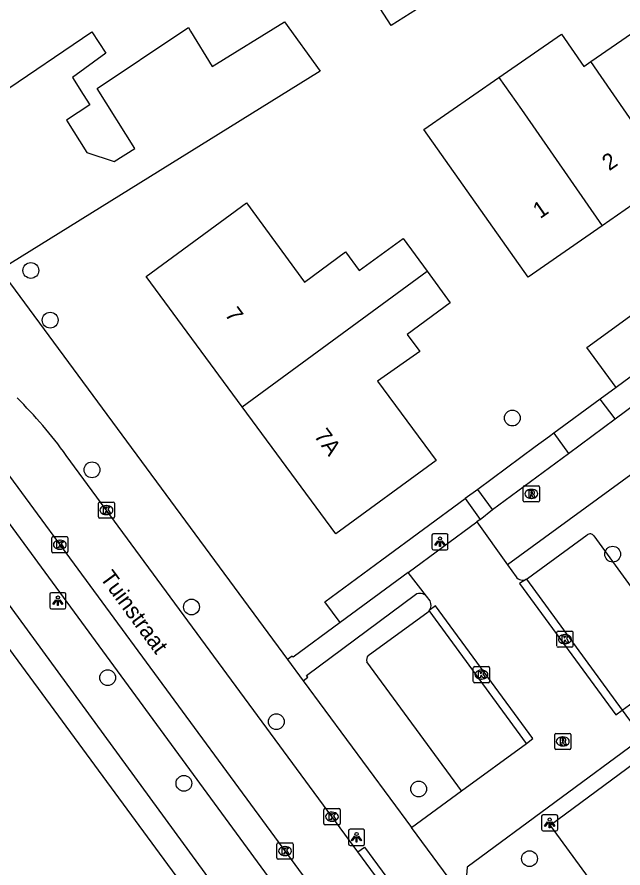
# Model space of a CAD drawing. Extents: x 161801 to 162379, y 382315 to 382832.
# Drawn here: x 161967 to 162004.5, y 382446.1 to 382498.8 of the extents above; entities that cross this region are included whole.
import ezdxf

# ---------------------------------------------------------------- set-up
doc = ezdxf.new("R2010")
doc.units = 0
for name, color, linetype in [('IMGEO_Boom', 7, 'Continuous'), ('IMGEO_Groenvoorziening', 7, 'Continuous'), ('IMGEO_Kolk', 7, 'Continuous'), ('IMGEO_Lichtpunt', 7, 'Continuous'), ('IMGEO_Openbare_ruimte_label', 7, 'Continuous'), ('IMGEO_Pand', 7, 'Continuous'), ('IMGEO_Pand_nummerreeks', 7, 'Continuous'), ('IMGEO_Parkeervlak_open', 7, 'Continuous'), ('IMGEO_Rijbaan_lokaal_open', 7, 'Continuous'), ('IMGEO_Rioolput', 7, 'Continuous'), ('IMGEO_Voetpad_open', 7, 'Continuous')]:
    doc.layers.add(name, color=color, linetype=linetype)

msp = doc.modelspace()

# ---------------------------------------------------------------- linework, layer by layer
at = {"layer": 'IMGEO_Boom'}
for centre in [(161967.865, 382483.121), (161969.063, 382480.043), (161997.697, 382473.976), (161971.654, 382470.771), (162003.909, 382465.545), (161977.814, 382462.27), (161972.621, 382457.894), (161983.07, 382455.167), (161977.348, 382451.352), (161991.892, 382450.996), (161998.756, 382446.683)]:
    msp.add_circle(centre, 0.489, dxfattribs=at)
at = {"layer": 'IMGEO_Groenvoorziening'}
for points in [[(162004.124, 382475.871), (162003.145, 382475.15)], [(162000.27, 382473.035), (162000, 382472.836), (161999.114, 382472.184), (161995.546, 382469.558)], [(161987.033, 382461.316), (161986.084, 382462.594), (161989.614, 382465.192), (161994.772, 382468.988)]]:
    msp.add_lwpolyline(points, dxfattribs=at)
at = {"layer": 'IMGEO_Kolk'}
for p, q in [((161972.046, 382467.848), (161972.046, 382468.7)), ((161972.121, 382468.774), (161972.973, 382468.774)), ((161972.534, 382468.554), (161972.559, 382468.554)), ((161973.047, 382468.7), (161973.047, 382467.848)), ((161972.557, 382467.994), (161972.532, 382467.994)), ((161972.973, 382467.774), (161972.121, 382467.774)), ((161969.16, 382465.704), (161969.16, 382466.556)), ((161969.235, 382466.63), (161970.087, 382466.63)), ((161969.648, 382466.41), (161969.673, 382466.41)), ((161970.161, 382466.556), (161970.161, 382465.704)), ((161970.087, 382465.63), (161969.235, 382465.63)), ((161969.671, 382465.85), (161969.646, 382465.85)), ((162000.451, 382459.856), (162000.451, 382460.708)), ((162000.526, 382460.782), (162001.378, 382460.782)), ((162001.452, 382460.708), (162001.452, 382459.856)), ((162000.939, 382460.562), (162000.964, 382460.562)), ((162001.378, 382459.782), (162000.526, 382459.782)), ((162000.962, 382460.002), (162000.937, 382460.002)), ((161995.277, 382457.657), (161995.277, 382458.509)), ((161995.352, 382458.583), (161996.204, 382458.583)), ((161996.278, 382458.509), (161996.278, 382457.657)), ((161995.765, 382458.363), (161995.79, 382458.363)), ((161996.204, 382457.583), (161995.352, 382457.583)), ((161995.788, 382457.803), (161995.763, 382457.803)), ((161986.02, 382448.856), (161986.02, 382449.708)), ((161986.095, 382449.782), (161986.947, 382449.782)), ((161986.508, 382449.562), (161986.533, 382449.562)), ((161987.021, 382449.708), (161987.021, 382448.856)), ((161986.947, 382448.782), (161986.095, 382448.782)), ((161986.531, 382449.002), (161986.506, 382449.002)), ((161983.111, 382446.727), (161983.111, 382447.579)), ((161983.186, 382447.653), (161984.038, 382447.653)), ((161983.599, 382447.433), (161983.624, 382447.433)), ((161984.112, 382447.579), (161984.112, 382446.727)), ((161984.038, 382446.653), (161983.186, 382446.653)), ((161983.622, 382446.873), (161983.597, 382446.873))]:
    msp.add_line(p, q, dxfattribs=at)
for points in [[(161972.046, 382467.848), (161972.046, 382468.7)], [(161972.121, 382468.774), (161972.973, 382468.774)], [(161973.047, 382468.7), (161973.047, 382467.848)], [(161972.367, 382468.474), (161972.49, 382468.474), (161972.49, 382468.323), (161972.62, 382468.474), (161972.784, 382468.474), (161972.638, 382468.323), (161972.791, 382468.074), (161972.639, 382468.074), (161972.554, 382468.238), (161972.49, 382468.171), (161972.49, 382468.074), (161972.367, 382468.074), (161972.367, 382468.474)], [(161972.973, 382467.774), (161972.121, 382467.774)], [(161969.16, 382465.704), (161969.16, 382466.556)], [(161969.235, 382466.63), (161970.087, 382466.63)], [(161970.161, 382466.556), (161970.161, 382465.704)], [(161969.481, 382466.33), (161969.604, 382466.33), (161969.604, 382466.179), (161969.734, 382466.33), (161969.898, 382466.33), (161969.752, 382466.179), (161969.905, 382465.93), (161969.753, 382465.93), (161969.668, 382466.094), (161969.604, 382466.027), (161969.604, 382465.93), (161969.481, 382465.93), (161969.481, 382466.33)], [(161970.087, 382465.63), (161969.235, 382465.63)], [(162000.451, 382459.856), (162000.451, 382460.708)], [(162000.526, 382460.782), (162001.378, 382460.782)], [(162001.452, 382460.708), (162001.452, 382459.856)], [(162000.772, 382460.482), (162000.895, 382460.482), (162000.895, 382460.331), (162001.025, 382460.482), (162001.189, 382460.482), (162001.043, 382460.331), (162001.196, 382460.082), (162001.044, 382460.082), (162000.959, 382460.246), (162000.895, 382460.179), (162000.895, 382460.082), (162000.772, 382460.082), (162000.772, 382460.482)], [(162001.378, 382459.782), (162000.526, 382459.782)], [(161995.277, 382457.657), (161995.277, 382458.509)], [(161995.352, 382458.583), (161996.204, 382458.583)], [(161996.278, 382458.509), (161996.278, 382457.657)], [(161995.598, 382458.283), (161995.721, 382458.283), (161995.721, 382458.132), (161995.851, 382458.283), (161996.015, 382458.283), (161995.869, 382458.132), (161996.022, 382457.883), (161995.87, 382457.883), (161995.785, 382458.047), (161995.721, 382457.98), (161995.721, 382457.883), (161995.598, 382457.883), (161995.598, 382458.283)], [(161996.204, 382457.583), (161995.352, 382457.583)], [(161986.02, 382448.856), (161986.02, 382449.708)], [(161986.095, 382449.782), (161986.947, 382449.782)], [(161987.021, 382449.708), (161987.021, 382448.856)], [(161986.341, 382449.482), (161986.464, 382449.482), (161986.464, 382449.331), (161986.594, 382449.482), (161986.758, 382449.482), (161986.612, 382449.331), (161986.765, 382449.082), (161986.613, 382449.082), (161986.528, 382449.246), (161986.464, 382449.179), (161986.464, 382449.082), (161986.341, 382449.082), (161986.341, 382449.482)], [(161986.947, 382448.782), (161986.095, 382448.782)], [(161983.111, 382446.727), (161983.111, 382447.579)], [(161983.186, 382447.653), (161984.038, 382447.653)], [(161984.112, 382447.579), (161984.112, 382446.727)], [(161983.432, 382447.353), (161983.555, 382447.353), (161983.555, 382447.202), (161983.685, 382447.353), (161983.849, 382447.353), (161983.703, 382447.202), (161983.856, 382446.953), (161983.704, 382446.953), (161983.619, 382447.117), (161983.555, 382447.05), (161983.555, 382446.953), (161983.432, 382446.953), (161983.432, 382447.353)], [(161984.038, 382446.653), (161983.186, 382446.653)]]:
    msp.add_lwpolyline(points, dxfattribs=at)
for centre, start, end in [((161972.123, 382468.698), 91.552, 178.448), ((161972.123, 382468.698), 91.552, 178.448), ((161972.971, 382468.698), 1.552, 88.448), ((161972.971, 382468.698), 1.552, 88.448), ((161972.123, 382467.85), 181.552, 268.448), ((161972.123, 382467.85), 181.552, 268.448), ((161972.971, 382467.85), 271.552, 358.448), ((161972.971, 382467.85), 271.552, 358.448), ((161969.237, 382466.554), 91.552, 178.448), ((161969.237, 382466.554), 91.552, 178.448), ((161970.085, 382466.554), 1.552, 88.448), ((161970.085, 382466.554), 1.552, 88.448), ((161969.237, 382465.706), 181.552, 268.448), ((161969.237, 382465.706), 181.552, 268.448), ((161970.085, 382465.706), 271.552, 358.448), ((161970.085, 382465.706), 271.552, 358.448), ((162000.528, 382460.706), 91.552, 178.448), ((162000.528, 382460.706), 91.552, 178.448), ((162001.376, 382460.706), 1.552, 88.448), ((162001.376, 382460.706), 1.552, 88.448), ((162000.528, 382459.858), 181.552, 268.448), ((162000.528, 382459.858), 181.552, 268.448), ((162001.376, 382459.858), 271.552, 358.448), ((162001.376, 382459.858), 271.552, 358.448), ((161995.354, 382458.507), 91.552, 178.448), ((161995.354, 382458.507), 91.552, 178.448), ((161996.202, 382458.507), 1.552, 88.448), ((161996.202, 382458.507), 1.552, 88.448), ((161995.354, 382457.659), 181.552, 268.448), ((161995.354, 382457.659), 181.552, 268.448), ((161996.202, 382457.659), 271.552, 358.448), ((161996.202, 382457.659), 271.552, 358.448), ((161986.097, 382449.706), 91.552, 178.448), ((161986.097, 382449.706), 91.552, 178.448), ((161986.945, 382449.706), 1.552, 88.448), ((161986.945, 382449.706), 1.552, 88.448), ((161986.097, 382448.858), 181.552, 268.448), ((161986.097, 382448.858), 181.552, 268.448), ((161986.945, 382448.858), 271.552, 358.448), ((161986.945, 382448.858), 271.552, 358.448), ((161983.188, 382447.577), 91.552, 178.448), ((161983.188, 382447.577), 91.552, 178.448), ((161984.036, 382447.577), 1.552, 88.448), ((161984.036, 382447.577), 1.552, 88.448), ((161983.188, 382446.729), 181.552, 268.448), ((161983.188, 382446.729), 181.552, 268.448), ((161984.036, 382446.729), 271.552, 358.448), ((161984.036, 382446.729), 271.552, 358.448)]:
    msp.add_arc(centre, 0.0765, start, end, dxfattribs=at)
for centre, major_axis, ratio, start_param, end_param in [((161972.533, 382468.274), (-0.387, 0.002), 0.722429, 4.712389, 7.853982), ((161972.558, 382468.274), (-0.39, 0.002), 0.717154, 1.570796, 4.712389), ((161969.647, 382466.13), (-0.387, 0.002), 0.722429, 4.712389, 7.853982), ((161969.672, 382466.13), (-0.39, 0.002), 0.717154, 1.570796, 4.712389), ((162000.938, 382460.282), (-0.387, 0.002), 0.722429, 4.712389, 7.853982), ((162000.963, 382460.282), (-0.39, 0.002), 0.717154, 1.570796, 4.712389), ((161995.764, 382458.083), (-0.387, 0.002), 0.722429, 4.712389, 7.853982), ((161995.789, 382458.083), (-0.39, 0.002), 0.717154, 1.570796, 4.712389), ((161986.507, 382449.282), (-0.387, 0.002), 0.722429, 4.712389, 7.853982), ((161986.532, 382449.282), (-0.39, 0.002), 0.717154, 1.570796, 4.712389), ((161983.598, 382447.153), (-0.387, 0.002), 0.722429, 4.712389, 7.853982), ((161983.623, 382447.153), (-0.39, 0.002), 0.717154, 1.570796, 4.712389)]:
    msp.add_ellipse(centre, major_axis=major_axis, ratio=ratio, start_param=start_param, end_param=end_param, dxfattribs=at)
at = {"layer": 'IMGEO_Lichtpunt'}
for p, q in [((161992.712, 382466.716), (161992.712, 382465.909)), ((161992.712, 382466.716), (161992.712, 382465.909)), ((161993.614, 382466.811), (161992.806, 382466.811)), ((161993.614, 382466.811), (161992.806, 382466.811)), ((161993.708, 382465.909), (161993.708, 382466.716)), ((161993.708, 382465.909), (161993.708, 382466.716)), ((161992.806, 382465.815), (161993.614, 382465.815)), ((161992.806, 382465.815), (161993.614, 382465.815)), ((161969.043, 382463.061), (161969.043, 382462.254)), ((161969.043, 382463.061), (161969.043, 382462.254)), ((161969.945, 382463.156), (161969.137, 382463.156)), ((161969.945, 382463.156), (161969.137, 382463.156)), ((161970.039, 382462.254), (161970.039, 382463.061)), ((161970.039, 382462.254), (161970.039, 382463.061)), ((161969.137, 382462.16), (161969.945, 382462.16)), ((161969.137, 382462.16), (161969.945, 382462.16)), ((161999.508, 382449.308), (161999.508, 382448.501)), ((161999.508, 382449.308), (161999.508, 382448.501)), ((162000.41, 382449.403), (161999.602, 382449.403)), ((162000.41, 382449.403), (161999.602, 382449.403)), ((162000.504, 382448.501), (162000.504, 382449.308)), ((162000.504, 382448.501), (162000.504, 382449.308)), ((161988.445, 382448.503), (161987.637, 382448.503)), ((161988.445, 382448.503), (161987.637, 382448.503)), ((161987.543, 382448.408), (161987.543, 382447.601)), ((161987.543, 382448.408), (161987.543, 382447.601)), ((161988.539, 382447.601), (161988.539, 382448.408)), ((161988.539, 382447.601), (161988.539, 382448.408)), ((161999.602, 382448.407), (162000.41, 382448.407)), ((161999.602, 382448.407), (162000.41, 382448.407)), ((161987.637, 382447.507), (161988.445, 382447.507)), ((161987.637, 382447.507), (161988.445, 382447.507))]:
    msp.add_line(p, q, dxfattribs=at)
for points in [[(161993.086, 382466.38), (161993.125, 382466.352), (161992.937, 382466.09), (161992.899, 382466.117), (161993.086, 382466.38)], [(161993.188, 382466.332), (161993.235, 382466.332), (161993.235, 382466.01), (161993.188, 382466.01), (161993.188, 382466.332)], [(161993.298, 382466.352), (161993.336, 382466.379), (161993.523, 382466.117), (161993.484, 382466.089), (161993.298, 382466.352)], [(161969.417, 382462.725), (161969.456, 382462.697), (161969.268, 382462.435), (161969.23, 382462.462), (161969.417, 382462.725)], [(161969.629, 382462.697), (161969.667, 382462.724), (161969.854, 382462.462), (161969.815, 382462.434), (161969.629, 382462.697)], [(161969.519, 382462.677), (161969.566, 382462.677), (161969.566, 382462.355), (161969.519, 382462.355), (161969.519, 382462.677)], [(161999.882, 382448.972), (161999.921, 382448.944), (161999.733, 382448.682), (161999.695, 382448.709), (161999.882, 382448.972)], [(161999.984, 382448.924), (162000.031, 382448.924), (162000.031, 382448.602), (161999.984, 382448.602), (161999.984, 382448.924)], [(162000.094, 382448.944), (162000.132, 382448.971), (162000.319, 382448.709), (162000.28, 382448.681), (162000.094, 382448.944)], [(161987.917, 382448.072), (161987.956, 382448.044), (161987.768, 382447.782), (161987.73, 382447.809), (161987.917, 382448.072)], [(161988.019, 382448.024), (161988.066, 382448.024), (161988.066, 382447.702), (161988.019, 382447.702), (161988.019, 382448.024)], [(161988.129, 382448.044), (161988.167, 382448.071), (161988.354, 382447.809), (161988.315, 382447.781), (161988.129, 382448.044)]]:
    msp.add_lwpolyline(points, dxfattribs=at)
for centre in [(161993.211, 382466.514), (161969.542, 382462.859), (162000.007, 382449.106), (161988.042, 382448.206)]:
    msp.add_circle(centre, 0.0994, dxfattribs=at)
for centre, start, end in [((161992.806, 382466.716), 90, 180), ((161992.806, 382466.716), 90, 180), ((161993.614, 382466.716), 0, 90), ((161993.614, 382466.716), 0, 90), ((161992.806, 382465.909), 180, 270), ((161992.806, 382465.909), 180, 270), ((161993.614, 382465.909), 270, 0), ((161993.614, 382465.909), 270, 360), ((161969.137, 382463.061), 90, 180), ((161969.137, 382463.061), 90, 180), ((161969.945, 382463.061), 0, 90), ((161969.945, 382463.061), 0, 90), ((161969.137, 382462.254), 180, 270), ((161969.137, 382462.254), 180, 270), ((161969.945, 382462.254), 270, 0), ((161969.945, 382462.254), 270, 360), ((161999.602, 382449.308), 90, 180), ((161999.602, 382449.308), 90, 180), ((162000.41, 382449.308), 0, 90), ((162000.41, 382449.308), 0, 90), ((161987.637, 382448.408), 90, 180), ((161987.637, 382448.408), 90, 180), ((161988.445, 382448.408), 0, 90), ((161988.445, 382448.408), 0, 90), ((161999.602, 382448.501), 180, 270), ((161999.602, 382448.501), 180, 270), ((162000.41, 382448.501), 270, 0), ((162000.41, 382448.501), 270, 360), ((161987.637, 382447.601), 180, 270), ((161987.637, 382447.601), 180, 270), ((161988.445, 382447.601), 270, 0), ((161988.445, 382447.601), 270, 360)]:
    msp.add_arc(centre, 0.0946, start, end, dxfattribs=at)
at = {"layer": 'IMGEO_Pand'}
for points in [[(161992.897, 382500.102), (161992.924, 382500.06), (161990.186, 382498.299), (161987.505, 382502.468), (161990.146, 382504.167)], [(162002.559, 382496.061), (162008.247, 382500), (162011.191, 382502.039)], [(161965.896, 382494.027), (161971.633, 382497.907), (161972.516, 382496.591), (161970.453, 382495.072), (161971.115, 382494.021), (161971.515, 382493.387), (161970.072, 382492.422), (161971.323, 382490.435), (161973.02, 382489.874), (161974.313, 382490.677), (161971.975, 382494.388), (161977.288, 382497.942), (161977.626, 382498.168), (161977.762, 382497.945), (161979.108, 382495.748), (161983.581, 382498.525), (161985.792, 382495.462), (161965.971, 382483.156)], [(161996.867, 382495.078), (162000.748, 382497.765), (162002.132, 382495.765), (162002.559, 382496.061)], [(162007.543, 382488.859), (162003.194, 382495.144), (162002.559, 382496.061)], [(162003.252, 382485.887), (161998.668, 382482.712), (161992.22, 382491.86), (161996.867, 382495.078)], [(161996.867, 382495.078), (161998.269, 382493.089), (162003.252, 382485.887)], [(162007.543, 382488.859), (162003.252, 382485.887)], [(161980.965, 382474.667), (161975.014, 382482.748), (161981.215, 382487.314), (161984.822, 382482.405), (161987.368, 382484.277), (161988.215, 382483.124), (161990.921, 382485.104), (161992.408, 382483.072)], [(161992.408, 382483.072), (161993.848, 382481.105), (161991.185, 382479.149), (161991.967, 382478.093), (161989.346, 382476.259), (161992.965, 382471.347), (161986.763, 382466.795), (161980.965, 382474.667)], [(161980.965, 382474.667), (161992.408, 382483.072)], [(162004.124, 382475.871), (162002.31, 382478.34), (162005.398, 382480.608), (162007.212, 382478.139)], [(162007.212, 382478.139), (162004.124, 382475.871)], [(161963.788, 382446.095), (161956.287, 382456.292), (161953.507, 382454.248), (161948.615, 382460.899), (161951.433, 382462.972), (161950.757, 382463.891), (161954.931, 382466.962), (161958.958, 382469.924), (161992.199, 382424.732)], [(162012.297, 382445.1), (162014.128, 382446.461), (162011.818, 382449.569), (162009.909, 382448.237), (162006.221, 382453.297), (162000.03, 382448.734), (162004.978, 382441.988), (162005.81, 382440.854), (162006.084, 382440.48)]]:
    msp.add_lwpolyline(points, dxfattribs=at)
at = {"layer": 'IMGEO_Parkeervlak_open'}
for points in [[(161998.562, 382463.992), (161998.632, 382464.037), (162002.325, 382466.739)], [(162002.74, 382466.671), (162008.289, 382459.041)], [(161988.761, 382459.265), (161992.481, 382461.979)], [(161994.548, 382450.89), (161988.675, 382458.883)]]:
    msp.add_lwpolyline(points, dxfattribs=at)
for centre, radius, start, end in [((162002.502, 382466.521), 0.281, 32.2401, 129.1488), ((161992.089, 382462.416), 0.587, 311.8745, 320.79), ((161989.108, 382458.986), 0.445, 141.2003, 193.4247)]:
    msp.add_arc(centre, radius, start, end, dxfattribs=at)
at = {"layer": 'IMGEO_Rijbaan_lokaal_open'}
for points in [[(161988.124, 382447.103), (161970.053, 382471.662)], [(161966.539, 382470.379), (161996.412, 382429.744)], [(161991.236, 382464.408), (161995.501, 382467.545)], [(161995.501, 382467.545), (161997.4, 382464.883)], [(161997.4, 382464.883), (161997.922, 382464.147)], [(161992.373, 382462.938), (161991.236, 382464.408)], [(161998.562, 382463.992), (161998.139, 382463.729), (162004.099, 382455.591), (162004.499, 382455.882)], [(161992.599, 382462.646), (161992.373, 382462.938)], [(161998.562, 382453.823), (161998.967, 382454.122), (161992.935, 382462.344), (161992.544, 382462.045)], [(162004.499, 382455.882), (162005.757, 382454.164)], [(162005.757, 382454.164), (161994.889, 382446.161), (161994.794, 382444.891), (161994.413, 382444.586)], [(161994.548, 382450.89), (161998.562, 382453.823)], [(161991.438, 382448.62), (161994.548, 382450.89)], [(161994.413, 382444.586), (161991.438, 382448.62)], [(161991.637, 382442.328), (161988.124, 382447.103)]]:
    msp.add_lwpolyline(points, dxfattribs=at)
for centre, radius, start, end in [((161948.128, 382456.007), 26.94, 35.5274, 45.5081), ((161998.329, 382464.427), 0.494, 214.579, 298.1926), ((161992.113, 382462.387), 0.55, 321.503, 28.0394)]:
    msp.add_arc(centre, radius, start, end, dxfattribs=at)
at = {"layer": 'IMGEO_Rioolput'}
for p, q in [((161998.372, 382468.853), (161998.372, 382469.705)), ((161998.447, 382469.779), (161999.299, 382469.779)), ((161999.373, 382469.705), (161999.373, 382468.853)), ((161998.86, 382469.559), (161998.885, 382469.559)), ((161999.299, 382468.779), (161998.447, 382468.779)), ((161998.883, 382468.999), (161998.858, 382468.999)), ((162000.317, 382453.519), (162000.317, 382454.371)), ((162000.392, 382454.445), (162001.244, 382454.445)), ((162001.318, 382454.371), (162001.318, 382453.519)), ((162000.805, 382454.225), (162000.83, 382454.225)), ((162001.244, 382453.445), (162000.392, 382453.445)), ((162000.828, 382453.665), (162000.803, 382453.665))]:
    msp.add_line(p, q, dxfattribs=at)
for points in [[(161998.372, 382468.853), (161998.372, 382469.705)], [(161998.447, 382469.779), (161999.299, 382469.779)], [(161999.373, 382469.705), (161999.373, 382468.853)], [(161998.961, 382469.477), (161998.709, 382469.479), (161998.709, 382469.079)], [(161998.709, 382469.079), (161998.833, 382469.079), (161998.833, 382469.241), (161998.844, 382469.241)], [(161998.887, 382469.398), (161998.833, 382469.398), (161998.833, 382469.317)], [(161998.833, 382469.317), (161998.885, 382469.317)], [(161998.891, 382469.212), (161998.962, 382469.079), (161999.102, 382469.079), (161999.037, 382469.205)], [(161999.299, 382468.779), (161998.447, 382468.779)], [(162000.317, 382453.519), (162000.317, 382454.371)], [(162000.392, 382454.445), (162001.244, 382454.445)], [(162001.318, 382454.371), (162001.318, 382453.519)], [(162000.906, 382454.143), (162000.654, 382454.145), (162000.654, 382453.745)], [(162000.654, 382453.745), (162000.778, 382453.745), (162000.778, 382453.907), (162000.789, 382453.907)], [(162000.832, 382454.064), (162000.778, 382454.064), (162000.778, 382453.983)], [(162000.778, 382453.983), (162000.83, 382453.983)], [(162000.836, 382453.878), (162000.907, 382453.745), (162001.047, 382453.745), (162000.982, 382453.871)], [(162001.244, 382453.445), (162000.392, 382453.445)]]:
    msp.add_lwpolyline(points, dxfattribs=at)
for centre, radius, start, end in [((161998.449, 382469.703), 0.0765, 91.552, 178.448), ((161998.449, 382469.703), 0.0765, 91.552, 178.448), ((161999.297, 382469.703), 0.0765, 1.552, 88.448), ((161999.297, 382469.703), 0.0765, 1.552, 88.448), ((161998.843, 382469.188), 0.0533, 26.0293, 88.6989), ((161998.869, 382469.506), 0.19, 274.7715, 282.9687), ((161998.893, 382469.302), 0.0964, 77.0061, 93.1865), ((161998.907, 382469.359), 0.0378, 276.6634, 79.6772), ((161998.96, 382469.367), 0.109, 350.3612, 89.416), ((161998.958, 382469.367), 0.112, 277.5842, 350.9817), ((161998.942, 382469.152), 0.108, 29.5134, 73.7905), ((161998.449, 382468.855), 0.0765, 181.552, 268.448), ((161998.449, 382468.855), 0.0765, 181.552, 268.448), ((161999.297, 382468.855), 0.0765, 271.552, 358.448), ((161999.297, 382468.855), 0.0765, 271.552, 358.448), ((162000.394, 382454.369), 0.0765, 91.552, 178.448), ((162000.394, 382454.369), 0.0765, 91.552, 178.448), ((162001.242, 382454.369), 0.0765, 1.552, 88.448), ((162001.242, 382454.369), 0.0765, 1.552, 88.448), ((162000.788, 382453.854), 0.0533, 26.0293, 88.6989), ((162000.814, 382454.172), 0.19, 274.7715, 282.9687), ((162000.838, 382453.968), 0.0964, 77.0061, 93.1865), ((162000.852, 382454.025), 0.0378, 276.6634, 79.6772), ((162000.905, 382454.033), 0.109, 350.3612, 89.416), ((162000.903, 382454.033), 0.112, 277.5842, 350.9817), ((162000.887, 382453.818), 0.108, 29.5134, 73.7905), ((162000.394, 382453.521), 0.0765, 181.552, 268.448), ((162000.394, 382453.521), 0.0765, 181.552, 268.448), ((162001.242, 382453.521), 0.0765, 271.552, 358.448), ((162001.242, 382453.521), 0.0765, 271.552, 358.448)]:
    msp.add_arc(centre, radius, start, end, dxfattribs=at)
for centre, major_axis, ratio, start_param, end_param in [((161998.859, 382469.279), (-0.387, 0.002), 0.722429, 4.712389, 7.853982), ((161998.884, 382469.279), (-0.39, 0.002), 0.717154, 1.570796, 4.712389), ((162000.804, 382453.945), (-0.387, 0.002), 0.722429, 4.712389, 7.853982), ((162000.829, 382453.945), (-0.39, 0.002), 0.717154, 1.570796, 4.712389)]:
    msp.add_ellipse(centre, major_axis=major_axis, ratio=ratio, start_param=start_param, end_param=end_param, dxfattribs=at)
at = {"layer": 'IMGEO_Voetpad_open'}
for points in [[(161965.971, 382483.156), (161983.764, 382459.026)], [(161998.059, 382419.476), (161983.404, 382439.272), (161954.726, 382478.543)], [(162004.068, 382473.92), (162008.16, 382476.967)], [(162003.145, 382475.15), (162000.27, 382473.035)], [(162004.068, 382473.92), (162003.145, 382475.15)], [(162001.181, 382471.785), (162004.068, 382473.92)], [(162000.27, 382473.035), (162001.181, 382471.785)], [(161996.468, 382468.315), (162001.181, 382471.785)], [(162006.029, 382471.189), (161997.4, 382464.883)], [(161995.546, 382469.558), (161994.772, 382468.988)], [(161996.468, 382468.315), (161995.546, 382469.558)], [(161994.772, 382468.988), (161995.699, 382467.691)], [(161995.699, 382467.691), (161996.468, 382468.315)], [(161995.699, 382467.691), (161995.501, 382467.545)], [(161993.315, 382430.945), (161966.551, 382467.446)], [(161991.236, 382464.408), (161987.033, 382461.316)], [(161998.562, 382463.992), (162004.499, 382455.882)], [(161984.744, 382457.697), (161985.026, 382457.933), (161984.946, 382458.022), (161991.7, 382463.036)], [(161998.562, 382453.823), (161992.544, 382462.045)], [(161987.033, 382461.316), (161984.106, 382459.163), (161984.052, 382459.232), (161983.764, 382459.026)], [(161983.764, 382459.026), (161984.744, 382457.697)], [(162004.499, 382455.882), (162007.669, 382458.194)], [(161984.744, 382457.697), (161991.438, 382448.62)], [(161988.124, 382447.103), (161988.526, 382447.399), (161992.039, 382442.624), (161991.637, 382442.328)]]:
    msp.add_lwpolyline(points, dxfattribs=at)
msp.add_arc((161991.978, 382462.582), 0.532, 41.9776, 121.4524, dxfattribs=at)

# ---------------------------------------------------------------- texts
at = {"layer": 'IMGEO_Openbare_ruimte_label'}
msp.add_text('Tuinstraat', height=1, rotation=306.297, dxfattribs=at).set_placement((161972.111, 382464.075))
at = {"layer": 'IMGEO_Pand_nummerreeks'}
for s, rotation, p in [('2', 34.7098, (162003.694, 382489.259)), ('1', 34.7109, (161999.412, 382486.293)), ('7', 306.3105, (161979.846, 382480.389)), ('7A', 306.3105, (161985.374, 382472.866))]:
    msp.add_text(s, height=1, rotation=rotation, dxfattribs=at).set_placement(p)

doc.saveas('drawing.dxf')
